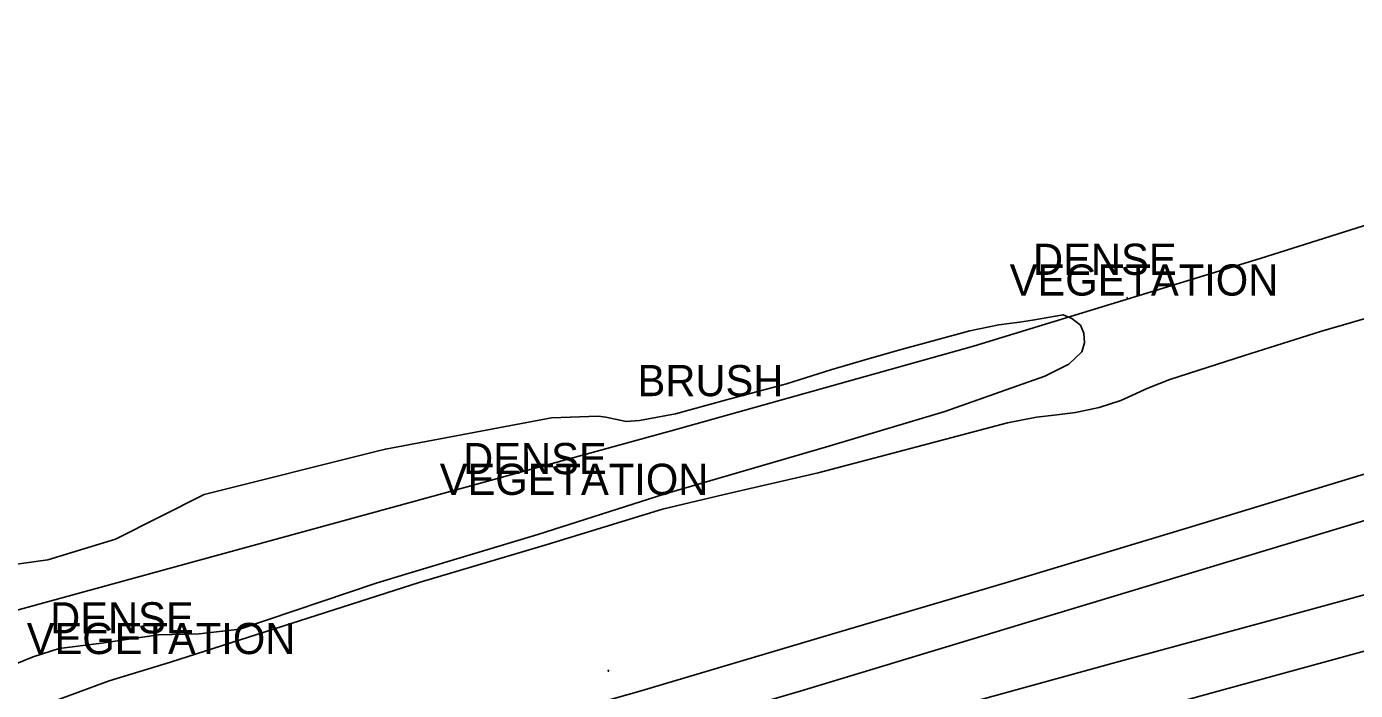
# Model space of a CAD drawing. Extents: x 2129547 to 2134906, y 657330 to 659734.
# Drawn here: x 2130233.3 to 2130531.7, y 658008.1 to 658157.2 of the extents above; entities that cross this region are included whole.
import ezdxf

# ---------------------------------------------------------------- set-up
doc = ezdxf.new("R2010")
doc.units = 0
for name, color, linetype in [('Default', 7, 'Continuous'), ('LT_X_Poles', 7, 'Continuous'), ('PM_X_Edge_Line', 7, 'Continuous'), ('PM_X_Lane_Line', 7, 'Continuous'), ('PV_X_EOP2', 7, 'Continuous'), ('PV_X_Shoulder', 7, 'Continuous'), ('RD_X_Fence', 7, 'Continuous'), ('SN_X_Public', 7, 'Continuous'), ('VG_X_Shrub_Line_Lt', 7, 'Continuous'), ('VG_X_Text', 7, 'Continuous'), ('VG_X_Tree_Line_Lt', 7, 'Continuous')]:
    doc.layers.add(name, color=color, linetype=linetype)

# ---------------------------------------------------------------- blocks, each defined once
blk = doc.blocks.new('POINT_DISPLAY')
at = {"layer": 'Default'}
blk.add_line((0, 0), (0, 0), dxfattribs=at)

msp = doc.modelspace()

# ---------------------------------------------------------------- linework, layer by layer
at = {"layer": 'LT_X_Poles'}
msp.add_lwpolyline([(2130363.97, 658012.75), (2130363.89, 658012.45), (2130364.01, 658012.45)], dxfattribs=at)
msp.add_circle((2130363.93, 658012.6), 0.065, dxfattribs=at)
at = {"layer": 'PM_X_Edge_Line'}
msp.add_lwpolyline([(2129783.9, 657836.03), (2129845.86, 657853.1), (2129914.14, 657872.06), (2129982.95, 657891.18), (2130034.97, 657905.36), (2130096.22, 657921.98), (2130157.01, 657938.72), (2130212.56, 657953.66), (2130267.72, 657968.86), (2130293.3, 657975.86), (2130314.89, 657981.71), (2130331.88, 657986.43), (2130357.23, 657993.47), (2130407.01, 658008.01), (2130461.65, 658024.51), (2130507.73, 658038.43), (2130546.43, 658050.14)], dxfattribs=at)
at = {"layer": 'PM_X_Lane_Line'}
for points in [[(2129783.61, 657823.91), (2129810.31, 657831.3), (2129849.13, 657842.04), (2129899.17, 657855.99), (2129939.24, 657867.08), (2129976.77, 657877.74), (2130017.08, 657888.49), (2130055.92, 657899.02), (2130096.18, 657909.94), (2130136.01, 657920.82), (2130175.79, 657931.24), (2130213.92, 657941.68), (2130252.44, 657952.34), (2130296.32, 657964.4), (2130319.63, 657970.79), (2130334.89, 657975.01), (2130359.14, 657981.71), (2130397.93, 657992.31), (2130437.8, 658003.41), (2130477.78, 658014.39), (2130517.26, 658025.11), (2130555.6, 658035.62)], [(2129783.29, 657810.14), (2129804.42, 657815.9), (2129840.99, 657826.02), (2129880.02, 657836.71), (2129920.48, 657848.01), (2129956.91, 657858.04), (2129996.24, 657869.42), (2130036.61, 657880.37), (2130073.22, 657890.36), (2130113.36, 657901.36), (2130150.86, 657911.7), (2130189.83, 657922.56), (2130229.83, 657933.62), (2130267.33, 657943.86), (2130299.45, 657952.54), (2130338.02, 657963.15), (2130345.77, 657965.28), (2130383.32, 657975.73), (2130422.46, 657986.54), (2130460.74, 657996.93), (2130499.23, 658007.56), (2130538.61, 658018.28)]]:
    msp.add_lwpolyline(points, dxfattribs=at)
at = {"layer": 'PV_X_EOP2'}
msp.add_lwpolyline([(2129783.9, 657836.03), (2129845.86, 657853.1), (2129914.14, 657872.06), (2129982.95, 657891.18), (2130034.97, 657905.36), (2130096.22, 657921.98), (2130157.01, 657938.72), (2130212.56, 657953.66), (2130267.72, 657968.86), (2130293.3, 657975.86), (2130314.89, 657981.71), (2130331.88, 657986.43), (2130357.23, 657993.47), (2130407.01, 658008.01), (2130461.65, 658024.51), (2130507.73, 658038.43), (2130546.43, 658050.14)], dxfattribs=at)
at = {"layer": 'PV_X_Shoulder'}
msp.add_lwpolyline([(2129784.13, 657845.78), (2129820.77, 657855.85), (2129911.85, 657881.4), (2129982.97, 657901.46), (2130035.32, 657915.88), (2130072.23, 657925.85), (2130123.9, 657939.97), (2130169.63, 657952.07), (2130213.34, 657964.08), (2130250.16, 657974.02), (2130290.75, 657985.53), (2130329.29, 657996.26), (2130330.56, 657996.61), (2130370.76, 658007.9), (2130412.81, 658020.38), (2130453.6, 658032.45), (2130494.01, 658044.69), (2130534.58, 658056.98)], dxfattribs=at)
at = {"layer": 'RD_X_Fence'}
msp.add_line((2130315.31, 658049.26), (2130276.74, 658038.66), dxfattribs=at)
for points in [[(2130675.45, 658157.25), (2130630.36, 658143.32), (2130575.2, 658125.7), (2130510.26, 658105.12), (2130445.93, 658085.48), (2130377.98, 658066.47), (2130315.31, 658049.26)], [(2130276.74, 658038.66), (2130175.12, 658010.79), (2129957.33, 657950.93)]]:
    msp.add_lwpolyline(points, dxfattribs=at)
at = {"layer": 'SN_X_Public'}
for p, q in [((2130480.48, 658096.37), (2130480.33, 658096.32)), ((2130480.38, 658096.34), (2130480.36, 658096.42)), ((2130480.43, 658096.35), (2130480.41, 658096.43))]:
    msp.add_line(p, q, dxfattribs=at)
at = {"layer": 'VG_X_Shrub_Line_Lt'}
for points in [[(2130561.25, 658099.58), (2130523.84, 658088.76), (2130506.75, 658083.39), (2130490.02, 658077.96), (2130485.03, 658076.05), (2130478.96, 658073.27), (2130474.14, 658071.69), (2130468.81, 658070.56), (2130464.03, 658069.98), (2130460.02, 658069.5), (2130453.57, 658068.26), (2130434.6, 658063.25), (2130411.04, 658057.01), (2130389.92, 658052.14), (2130376.09, 658048.85), (2130350.14, 658040.91), (2130321.62, 658032.43), (2130265.59, 658014.49)], [(2130265.59, 658014.49), (2130251.84, 658010.32), (2130236.4, 658004.62), (2130220.27, 657998.48), (2130215.14, 657996.5), (2130211.21, 657995), (2130209.68, 657994.58), (2130208.73, 657994.71), (2130208.58, 657995.44), (2130210.79, 658001.16), (2130214.98, 658010.69)]]:
    msp.add_lwpolyline(points, dxfattribs=at)
at = {"layer": 'VG_X_Tree_Line_Lt'}
msp.add_line((2130273.18, 658052.15), (2130311.98, 658061.89), dxfattribs=at)
for points in [[(2130311.98, 658061.89), (2130313.84, 658062.36), (2130351.16, 658069.4), (2130361.66, 658069.76), (2130363.34, 658069.55), (2130367.93, 658068.56), (2130370.9, 658068.75), (2130378.99, 658070.23), (2130390.43, 658073.38), (2130403.95, 658076.99), (2130413.88, 658080.12), (2130422.53, 658082.69), (2130429.7, 658084.73), (2130445.06, 658088.92), (2130451.6, 658090.25), (2130456.26, 658090.88), (2130459.15, 658091.33), (2130466.04, 658092.53), (2130467.99, 658091.69), (2130469.92, 658090.2), (2130470.69, 658088.4), (2130470.84, 658086.24), (2130470.23, 658084.18), (2130467.32, 658081.43), (2130461.93, 658078.71), (2130439.5, 658070.77), (2130412.67, 658062.77), (2130376.7, 658052.29), (2130348.11, 658043.18), (2130319.21, 658034.48)], [(2130281.15, 658021.92), (2130272.03, 658020.82), (2130262.88, 658020.66), (2130250.06, 658018.74), (2130240.57, 658017.58), (2130234.72, 658015.7), (2130224.97, 658011.71), (2130218.74, 658010.15), (2130214.98, 658010.69), (2130212.91, 658012.47), (2130212.41, 658013.96), (2130212.12, 658017.16), (2130213.22, 658020.86), (2130215.55, 658022.97), (2130217.74, 658026.04), (2130220.14, 658029.97), (2130225.73, 658034.24), (2130229.94, 658036.34), (2130238.01, 658037.49), (2130253.22, 658042.08), (2130273.18, 658052.15)], [(2130319.21, 658034.48), (2130311.74, 658032.24), (2130281.15, 658021.92)]]:
    msp.add_lwpolyline(points, dxfattribs=at)

# ---------------------------------------------------------------- block references
at = {"layer": 'SN_X_Public', "xscale": 3.937000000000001, "yscale": 3.9370000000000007, "rotation": -74.35093535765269}
msp.add_blockref('POINT_DISPLAY', (2130480.4, 658096.35), dxfattribs=at)

# ---------------------------------------------------------------- texts
at = {"layer": 'VG_X_Text'}
for s, p in [('DENSE', (2130459.27, 658101.48)), ('VEGETATION', (2130454.02, 658096.82)), ('BRUSH', (2130370.46, 658074.23)), ('DENSE', (2130331.29, 658056.72)), ('VEGETATION', (2130326.04, 658052.06)), ('DENSE', (2130238.55, 658020.95)), ('VEGETATION', (2130233.3, 658016.3))]:
    msp.add_text(s, height=7, dxfattribs=at).set_placement(p)

doc.saveas('drawing.dxf')
